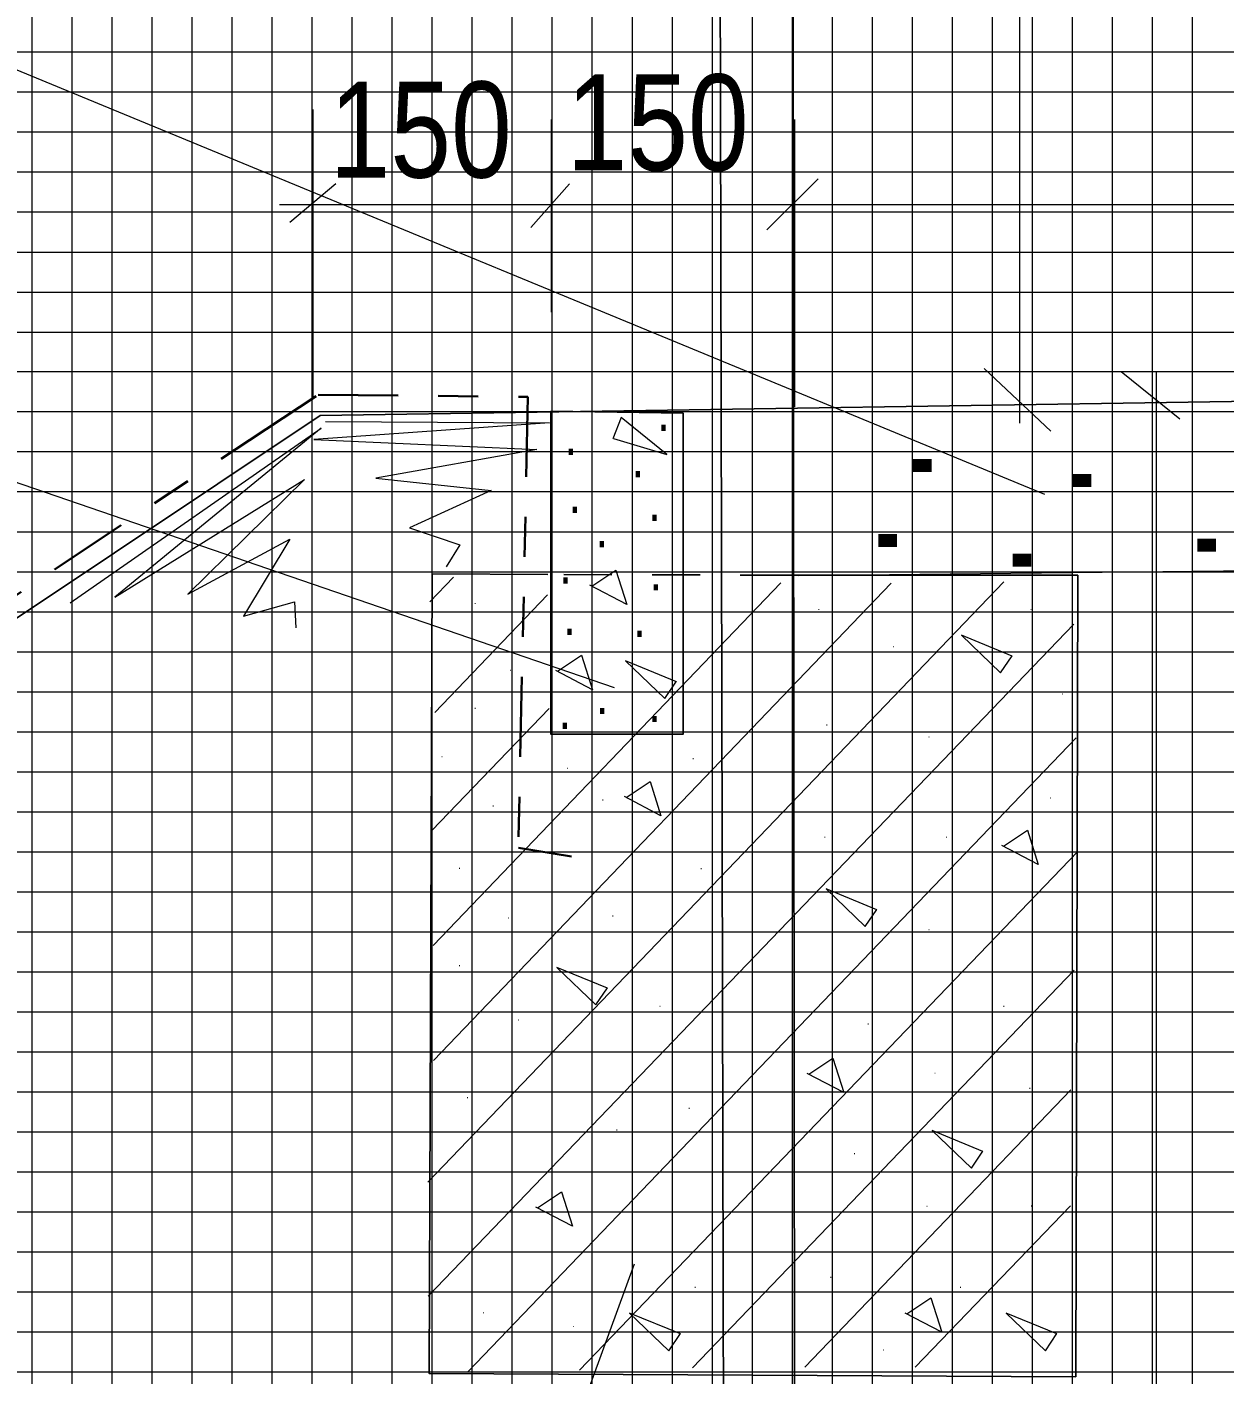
# Model space of a CAD drawing. Extents: x -265.4 to -236, y -5.8 to 40.6.
# Drawn here: x -247.828 to -244.837, y 7.705 to 11.072 of the extents above; entities that cross this region are included whole.
import ezdxf
from ezdxf.enums import TextEntityAlignment as Align

# ---------------------------------------------------------------- set-up
doc = ezdxf.new("R2010")
doc.units = 0
doc.header["$LTSCALE"] = 0.04
doc.linetypes.add('DASH_DOUBLE_DOT', pattern=[9.2, 5, -1.2, 0.3, -1.2, 0.3, -1.2])
doc.linetypes.add('MEDIUM_DASHED', pattern=[4.5, 3, -1.5])
for name, color, linetype, lineweight in [('1', 7, 'Continuous', 13), ('2', 7, 'MEDIUM_DASHED', 13), ('3', 7, 'Continuous', 13), ('4', 7, 'Continuous', 35), ('63', 7, 'Continuous', 13)]:
    doc.layers.add(name, color=color, linetype=linetype, lineweight=lineweight)

msp = doc.modelspace()

# ---------------------------------------------------------------- linework, layer by layer
at = {"layer": '1'}
for p, q in [((-247.816, 15.11), (-247.816, -5.836)), ((-247.716, 15.11), (-247.716, -5.836)), ((-247.516, 15.11), (-247.516, -5.836)), ((-247.416, 15.11), (-247.416, -5.836)), ((-247.316, 15.11), (-247.316, -5.836)), ((-247.216, 15.11), (-247.216, -5.836)), ((-247.016, 15.11), (-247.016, -5.836)), ((-246.916, 15.11), (-246.916, -5.836)), ((-246.816, 15.11), (-246.816, -5.836)), ((-246.716, 15.11), (-246.716, -5.836)), ((-246.516, 15.11), (-246.516, -5.836)), ((-246.416, 15.11), (-246.416, -5.836)), ((-246.316, 15.11), (-246.316, -5.836)), ((-246.216, 15.11), (-246.216, -5.836)), ((-246.016, 15.11), (-246.016, -5.836)), ((-245.916, 15.11), (-245.916, -5.836)), ((-245.816, 15.11), (-245.816, -5.836)), ((-245.716, 15.11), (-245.716, -5.836)), ((-245.516, 15.11), (-245.516, -5.836)), ((-245.416, 15.11), (-245.416, -5.836)), ((-245.316, 15.11), (-245.316, -5.836)), ((-245.216, 15.11), (-245.216, -5.836)), ((-245.016, 15.11), (-245.016, -5.836)), ((-244.916, 15.11), (-244.916, -5.836)), ((-265.117, 11.009), (-236.007, 11.009)), ((-265.117, 10.909), (-236.007, 10.909)), ((-265.117, 10.809), (-236.007, 10.809)), ((-265.117, 10.709), (-236.007, 10.709)), ((-265.117, 10.509), (-236.007, 10.509)), ((-265.117, 10.409), (-236.007, 10.409)), ((-265.117, 10.309), (-236.007, 10.309)), ((-265.117, 10.21), (-236.007, 10.21)), ((-265.117, 10.01), (-236.007, 10.01)), ((-265.117, 9.91), (-236.007, 9.91)), ((-265.117, 9.81), (-236.007, 9.81)), ((-265.117, 9.71), (-236.007, 9.71)), ((-265.117, 9.51), (-236.007, 9.51)), ((-265.117, 9.41), (-236.007, 9.41)), ((-265.117, 9.31), (-236.007, 9.31)), ((-265.117, 9.21), (-236.007, 9.21)), ((-265.117, 9.01), (-236.007, 9.01)), ((-265.117, 8.91), (-236.007, 8.91)), ((-265.117, 8.81), (-236.007, 8.81)), ((-265.117, 8.71), (-236.007, 8.71)), ((-265.117, 8.51), (-236.007, 8.51)), ((-265.117, 8.41), (-236.007, 8.41)), ((-265.117, 8.31), (-236.007, 8.31)), ((-265.117, 8.21), (-236.007, 8.21)), ((-265.117, 8.01), (-236.007, 8.01)), ((-265.117, 7.91), (-236.007, 7.91)), ((-265.117, 7.81), (-236.007, 7.81)), ((-265.117, 7.71), (-236.007, 7.71))]:
    msp.add_line(p, q, dxfattribs=at)
at = {"layer": '2', "linetype": 'Continuous'}
for p, q in [((-247.616, 15.11), (-247.616, -5.836)), ((-246.616, 15.11), (-246.616, -5.836)), ((-245.616, 15.11), (-245.616, -5.836)), ((-265.117, 10.609), (-236.007, 10.609)), ((-265.117, 9.61), (-236.007, 9.61)), ((-265.117, 8.61), (-236.007, 8.61))]:
    msp.add_line(p, q, dxfattribs=at)
at = {"layer": '3'}
for p, q in [((-247.116, 15.11), (-247.116, -5.836)), ((-246.116, 15.11), (-246.116, -5.836)), ((-265.117, 9.11), (-236.007, 9.11)), ((-265.117, 8.11), (-236.007, 8.11))]:
    msp.add_line(p, q, dxfattribs=at)
at = {"layer": '4', "lineweight": 13}
for p, q in [((-245.116, 15.11), (-245.116, -5.836)), ((-265.117, 10.11), (-236.007, 10.11))]:
    msp.add_line(p, q, dxfattribs=at)
at = {"layer": '63'}
for p, q in [((-245.348, 15.011), (-245.348, 10.081)), ((-247.113, 10.141), (-247.113, 10.865)), ((-246.517, 10.359), (-246.517, 10.84)), ((-245.909, 10.122), (-245.909, 10.84)), ((-247.056, 10.679), (-247.171, 10.583)), ((-246.472, 10.679), (-246.569, 10.57)), ((-245.851, 10.692), (-245.979, 10.564)), ((-247.197, 10.628), (-241.045, 10.628)), ((-245.436, 10.218), (-245.269, 10.061)), ((-245.094, 10.21), (-244.947, 10.092)), ((-245.006, 10.21), (-245.006, 6.074)), ((-241.136, 9.75), (-245.9, 9.7)), ((-245.387, 9.685), (-246.826, 8.184)), ((-246.762, 9.696), (-246.821, 9.635)), ((-245.944, 9.682), (-246.813, 8.776)), ((-245.668, 9.681), (-246.812, 8.488)), ((-246.527, 9.652), (-246.809, 9.358)), ((-245.212, 9.579), (-246.825, 7.899)), ((-246.523, 9.368), (-246.816, 9.063)), ((-245.206, 9.295), (-246.726, 7.71)), ((-245.203, 9.01), (-246.447, 7.714)), ((-245.211, 8.714), (-246.165, 7.72)), ((-245.219, 8.415), (-245.884, 7.722)), ((-245.22, 8.125), (-245.608, 7.722))]:
    msp.add_line(p, q, dxfattribs=at)
at = {"layer": '63', "linetype": 'MEDIUM_DASHED', "lineweight": 25}
msp.add_line((-245.926, 9.701), (-246.526, 9.703), dxfattribs=at)
at = {"layer": '63', "lineweight": 25}
for points in [[(-245.917, 13.983), (-245.908, 6.098), (-246.084, 6.098), (-246.104, 14.893), (-245.927, 14.893)], [(-246.519, 10.111), (-246.519, 9.304), (-246.188, 9.304), (-246.188, 10.106)]]:
    msp.add_lwpolyline(points, close=True, dxfattribs=at)
at = {"layer": '63'}
for points in [[(-245.284, 9.903), (-248.025, 11.034), (-253.914, 11.034)], [(-247.72, 9.632), (-247.093, 10.069), (-247.608, 9.646), (-247.134, 9.94), (-247.426, 9.654), (-247.171, 9.791), (-247.287, 9.599), (-247.159, 9.635), (-247.156, 9.57)], [(-247.082, 10.085), (-246.522, 10.082), (-247.111, 10.04), (-246.554, 10.015), (-246.956, 9.944), (-246.668, 9.913), (-246.872, 9.82), (-246.746, 9.777), (-246.78, 9.722)], [(-246.362, 10.043), (-246.229, 10.003), (-246.343, 10.095), (-246.364, 10.042)], [(-246.36, 9.42), (-248.173, 10.042), (-254.314, 10.042)], [(-246.416, 9.674), (-246.356, 9.714), (-246.329, 9.628), (-246.421, 9.676)], [(-245.366, 9.499), (-245.493, 9.551), (-245.395, 9.457), (-245.366, 9.5)], [(-246.502, 9.461), (-246.442, 9.501), (-246.415, 9.415), (-246.506, 9.463)], [(-246.205, 9.435), (-246.332, 9.487), (-246.234, 9.393), (-246.205, 9.436)], [(-246.331, 9.146), (-246.271, 9.186), (-246.244, 9.1), (-246.335, 9.148)], [(-245.388, 9.024), (-245.328, 9.064), (-245.301, 8.978), (-245.392, 9.026)], [(-245.704, 8.865), (-245.831, 8.917), (-245.733, 8.823), (-245.704, 8.866)], [(-246.377, 8.669), (-246.504, 8.721), (-246.406, 8.627), (-246.377, 8.67)], [(-245.874, 8.454), (-245.814, 8.494), (-245.787, 8.408), (-245.878, 8.456)], [(-245.439, 8.261), (-245.566, 8.313), (-245.468, 8.219), (-245.439, 8.262)], [(-246.552, 8.12), (-246.492, 8.16), (-246.465, 8.074), (-246.556, 8.122)], [(-246.311, 7.979), (-246.762, 6.742), (-251.297, 6.742)], [(-245.629, 7.855), (-245.569, 7.895), (-245.542, 7.809), (-245.633, 7.857)], [(-246.195, 7.805), (-246.322, 7.857), (-246.224, 7.763), (-246.195, 7.806)], [(-245.254, 7.805), (-245.381, 7.857), (-245.283, 7.763), (-245.254, 7.806)]]:
    msp.add_lwpolyline(points, dxfattribs=at)
at = {"layer": '63', "lineweight": 25}
for points in [[(-241.13, 10.192), (-247.095, 10.1), (-252.481, 6.504)], [(-245.926, 9.701), (-245.202, 9.701), (-245.207, 7.698), (-246.823, 7.706), (-246.815, 9.705), (-246.526, 9.703)]]:
    msp.add_lwpolyline(points, dxfattribs=at)
at = {"layer": '63', "linetype": 'DASH_DOUBLE_DOT', "lineweight": 35}
msp.add_lwpolyline([(-252.422, 6.614), (-247.272, 10.039), (-247.1, 10.152), (-246.576, 10.147), (-246.6, 9.02), (-246.467, 8.998)], dxfattribs=at)

# ---------------------------------------------------------------- texts
at = {"layer": '63'}
for s, height, width, p in [('150', 0.24, 0.85, (-246.252, 10.713)), ('150', 0.24, 0.85, (-246.844, 10.695)), ('.', 0.1, 0.85, (-246.2375, 10.062)), ('.', 0.1, 0.85, (-246.4685, 10.002)), ('.', 0.1, 0.85, (-246.3015, 9.946)), ('.', 0.1, 0.85, (-246.4585, 9.857)), ('.', 0.1, 0.85, (-246.2595, 9.837)), ('.', 0.1, 0.85, (-246.3915, 9.771)), ('.', 0.1, 0.85, (-246.4825, 9.68)), ('.', 0.1, 0.85, (-246.2565, 9.663)), ('.', 0.02, 0.8, (-246.708, 9.629)), ('.', 0.02, 0.8, (-245.849, 9.614)), ('.', 0.02, 0.8, (-245.319, 9.614)), ('.', 0.1, 0.85, (-246.4725, 9.552)), ('.', 0.1, 0.85, (-246.2975, 9.547)), ('.', 0.02, 0.8, (-245.662, 9.521)), ('.', 0.02, 0.8, (-246.619, 9.462)), ('.', 0.02, 0.8, (-245.24, 9.403)), ('.', 0.02, 0.8, (-246.708, 9.367)), ('.', 0.1, 0.85, (-246.3905, 9.354)), ('.', 0.1, 0.85, (-246.4835, 9.317)), ('.', 0.1, 0.85, (-246.2595, 9.334)), ('.', 0.02, 0.8, (-245.829, 9.325)), ('.', 0.02, 0.8, (-245.574, 9.295)), ('.', 0.02, 0.8, (-246.791, 9.246)), ('.', 0.02, 0.8, (-246.163, 9.241)), ('.', 0.02, 0.8, (-246.477, 9.217)), ('.', 0.02, 0.8, (-246.663, 9.123)), ('.', 0.02, 0.8, (-246.389, 9.138)), ('.', 0.02, 0.8, (-245.27, 9.143)), ('.', 0.02, 0.8, (-245.834, 9.045)), ('.', 0.02, 0.8, (-245.53, 9.045)), ('.', 0.02, 0.8, (-246.747, 8.967)), ('.', 0.02, 0.8, (-246.143, 8.966)), ('.', 0.02, 0.8, (-246.624, 8.843)), ('.', 0.02, 0.8, (-246.364, 8.848)), ('.', 0.02, 0.8, (-245.574, 8.814)), ('.', 0.02, 0.8, (-246.747, 8.724)), ('.', 0.02, 0.8, (-246.246, 8.622)), ('.', 0.02, 0.8, (-245.387, 8.622)), ('.', 0.02, 0.8, (-246.6, 8.588)), ('.', 0.02, 0.8, (-245.726, 8.578)), ('.', 0.02, 0.8, (-245.559, 8.455)), ('.', 0.02, 0.8, (-245.322, 8.417)), ('.', 0.02, 0.8, (-246.727, 8.394)), ('.', 0.02, 0.8, (-246.173, 8.367)), ('.', 0.02, 0.8, (-246.516, 8.343)), ('.', 0.02, 0.8, (-246.354, 8.313)), ('.', 0.02, 0.8, (-245.76, 8.254)), ('.', 0.02, 0.8, (-246.715, 8.139)), ('.', 0.02, 0.8, (-245.579, 8.122)), ('.', 0.02, 0.8, (-245.318, 8.123)), ('.', 0.02, 0.8, (-246.315, 8.023)), ('.', 0.02, 0.8, (-245.819, 7.945)), ('.', 0.02, 0.8, (-246.158, 7.92)), ('.', 0.02, 0.8, (-245.495, 7.92)), ('.', 0.02, 0.8, (-246.687, 7.856)), ('.', 0.02, 0.8, (-246.462, 7.822)), ('.', 0.02, 0.8, (-245.687, 7.763))]:
    msp.add_text(s, height=height, dxfattribs=dict(at, width=width)).set_placement(p, align=Align.CENTER)
at = {"layer": '63', "width": 0.85}
for p in [(-245.567, 9.975), (-245.168, 9.938), (-245.654, 9.788), (-244.857, 9.776), (-245.318, 9.739)]:
    msp.add_text('.', height=0.3, rotation=90, dxfattribs=at).set_placement(p, align=Align.CENTER)

doc.saveas('drawing.dxf')
